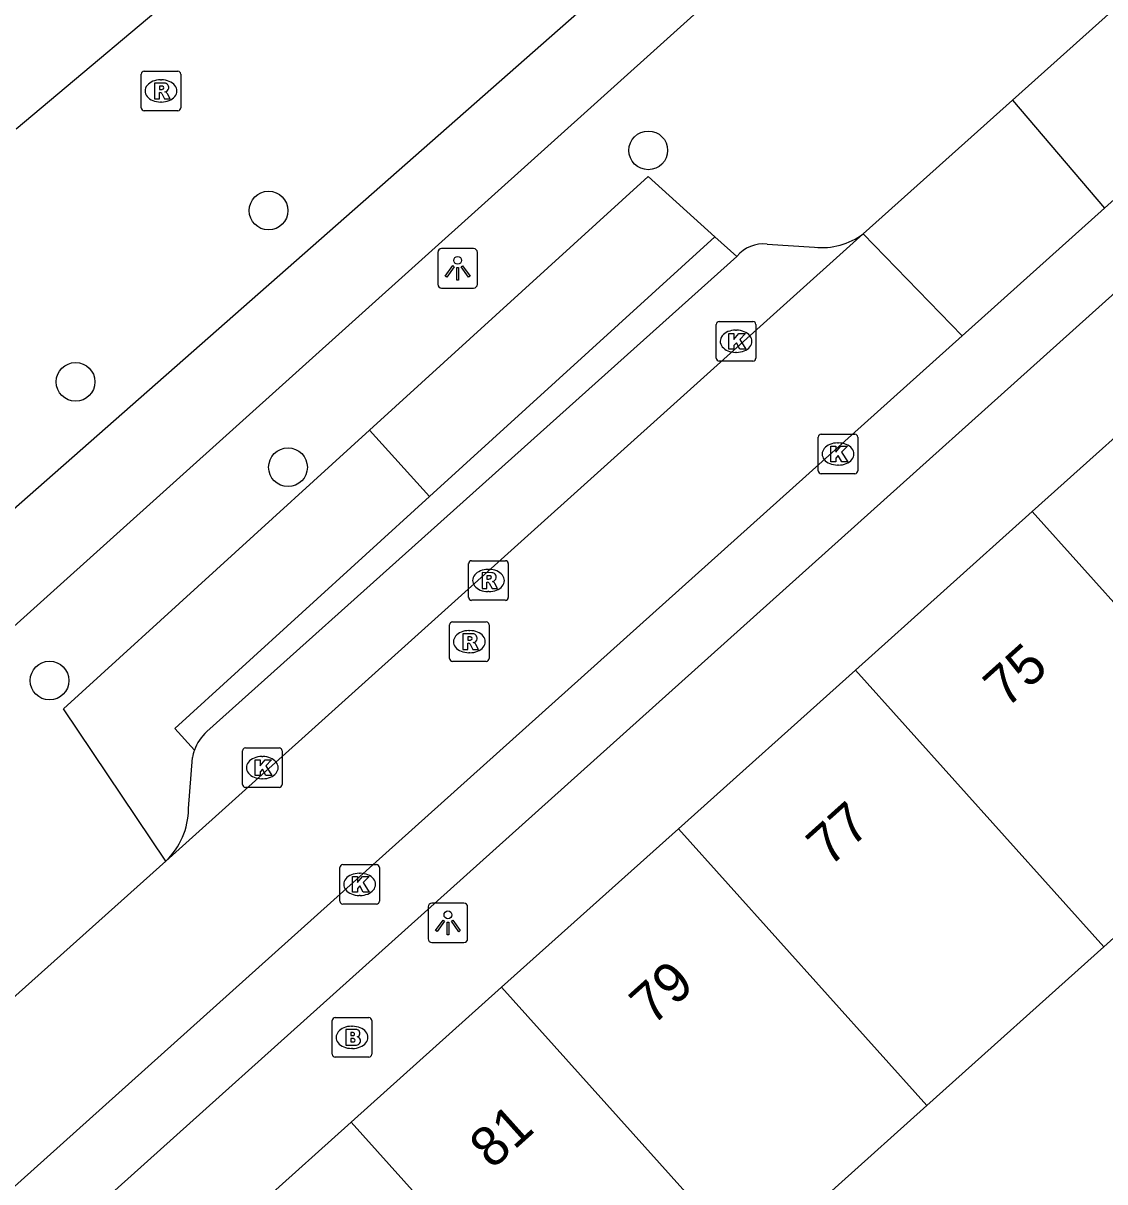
# Model space of a CAD drawing. Extents: x 162172 to 163187, y 382874 to 383684.
# Drawn here: x 162784.58 to 162811.9, y 383341 to 383370.27 of the extents above; entities that cross this region are included whole.
import ezdxf

# ---------------------------------------------------------------- set-up
doc = ezdxf.new("R2010")
doc.units = 0
for name, color, linetype in [('IMGEO_Berm_groen', 7, 'Continuous'), ('IMGEO_Boom', 7, 'Continuous'), ('IMGEO_Brandkraan', 7, 'Continuous'), ('IMGEO_Kolk', 7, 'Continuous'), ('IMGEO_Lichtpunt', 7, 'Continuous'), ('IMGEO_Pand', 7, 'Continuous'), ('IMGEO_Pand_nummerreeks', 7, 'Continuous'), ('IMGEO_Parkeervlak_open', 7, 'Continuous'), ('IMGEO_Rijbaan_lokaal_open', 7, 'Continuous'), ('IMGEO_Rioolput', 7, 'Continuous'), ('IMGEO_Voetpad_halfverhard', 7, 'Continuous'), ('IMGEO_Voetpad_open', 7, 'Continuous')]:
    doc.layers.add(name, color=color, linetype=linetype)

msp = doc.modelspace()

# ---------------------------------------------------------------- linework, layer by layer
at = {"layer": 'IMGEO_Berm_groen'}
for points in [[(162793.329, 383359.988), (162800.361, 383366.393), (162802.051, 383364.873)], [(162788.183, 383349.104), (162785.604, 383352.953), (162793.329, 383359.988)], [(162794.844, 383358.31), (162793.329, 383359.988)]]:
    msp.add_lwpolyline(points, dxfattribs=at)
at = {"layer": 'IMGEO_Boom'}
for centre in [(162800.368, 383367.055), (162790.778, 383365.534), (162785.905, 383361.208), (162791.27, 383359.051), (162785.248, 383353.663)]:
    msp.add_circle(centre, 0.489, dxfattribs=at)
at = {"layer": 'IMGEO_Brandkraan'}
for p, q in [((162792.461, 383345.151), (162793.313, 383345.151)), ((162792.386, 383344.225), (162792.386, 383345.077)), ((162792.874, 383344.931), (162792.899, 383344.931)), ((162793.387, 383345.077), (162793.387, 383344.225)), ((162792.897, 383344.371), (162792.872, 383344.371)), ((162793.313, 383344.151), (162792.461, 383344.151))]:
    msp.add_line(p, q, dxfattribs=at)
for points in [[(162792.461, 383345.151), (162793.313, 383345.151)], [(162792.386, 383344.225), (162792.386, 383345.077)], [(162792.734, 383344.851), (162792.734, 383344.451), (162792.947, 383344.451)], [(162792.965, 383344.851), (162792.734, 383344.851)], [(162793.387, 383345.077), (162793.387, 383344.225)], [(162792.913, 383344.77), (162792.859, 383344.77), (162792.859, 383344.694)], [(162792.859, 383344.694), (162792.912, 383344.694)], [(162792.921, 383344.618), (162792.859, 383344.618), (162792.859, 383344.537)], [(162792.859, 383344.537), (162792.921, 383344.537)], [(162793.313, 383344.151), (162792.461, 383344.151)]]:
    msp.add_lwpolyline(points, dxfattribs=at)
for centre, radius, start, end in [((162792.463, 383345.075), 0.0765, 91.552, 178.448), ((162792.463, 383345.075), 0.0765, 91.552, 178.448), ((162793.311, 383345.075), 0.0765, 1.552, 88.448), ((162793.311, 383345.075), 0.0765, 1.552, 88.448), ((162792.969, 383344.706), 0.145, 59.4692, 91.5367), ((162792.994, 383344.753), 0.0922, 285.5137, 58.1501), ((162792.914, 383344.732), 0.0379, 267.8285, 90.9355), ((162792.922, 383344.577), 0.0404, 269.8759, 90.5077), ((162792.999, 383344.561), 0.105, 301.3115, 78.989), ((162792.953, 383344.702), 0.251, 268.6676, 293.5347), ((162792.463, 383344.227), 0.0765, 181.552, 268.448), ((162792.463, 383344.227), 0.0765, 181.552, 268.448), ((162793.311, 383344.227), 0.0765, 271.552, 358.448), ((162793.311, 383344.227), 0.0765, 271.552, 358.448)]:
    msp.add_arc(centre, radius, start, end, dxfattribs=at)
for centre, major_axis, ratio, start_param, end_param in [((162792.873, 383344.651), (-0.387, 0.002), 0.722429, 4.712389, 7.853982), ((162792.898, 383344.651), (-0.39, 0.002), 0.717154, 1.570796, 4.712389)]:
    msp.add_ellipse(centre, major_axis=major_axis, ratio=ratio, start_param=start_param, end_param=end_param, dxfattribs=at)
at = {"layer": 'IMGEO_Kolk'}
for p, q in [((162802.159, 383362.733), (162803.011, 383362.733)), ((162802.084, 383361.807), (162802.084, 383362.659)), ((162802.572, 383362.513), (162802.597, 383362.513)), ((162803.085, 383362.659), (162803.085, 383361.807)), ((162802.595, 383361.953), (162802.57, 383361.953)), ((162803.011, 383361.733), (162802.159, 383361.733)), ((162804.659, 383358.96), (162804.659, 383359.812)), ((162804.734, 383359.886), (162805.586, 383359.886)), ((162805.66, 383359.812), (162805.66, 383358.96)), ((162805.147, 383359.666), (162805.172, 383359.666)), ((162805.586, 383358.886), (162804.734, 383358.886)), ((162805.17, 383359.106), (162805.145, 383359.106)), ((162790.119, 383351.038), (162790.119, 383351.89)), ((162790.194, 383351.964), (162791.046, 383351.964)), ((162791.12, 383351.89), (162791.12, 383351.038)), ((162790.607, 383351.744), (162790.632, 383351.744)), ((162790.63, 383351.184), (162790.605, 383351.184)), ((162791.046, 383350.964), (162790.194, 383350.964)), ((162792.578, 383348.089), (162792.578, 383348.941)), ((162792.653, 383349.015), (162793.505, 383349.015)), ((162793.579, 383348.941), (162793.579, 383348.089)), ((162793.066, 383348.795), (162793.091, 383348.795)), ((162793.089, 383348.235), (162793.064, 383348.235)), ((162793.505, 383348.015), (162792.653, 383348.015))]:
    msp.add_line(p, q, dxfattribs=at)
for points in [[(162802.159, 383362.733), (162803.011, 383362.733)], [(162802.084, 383361.807), (162802.084, 383362.659)], [(162802.405, 383362.433), (162802.528, 383362.433), (162802.528, 383362.282), (162802.658, 383362.433), (162802.822, 383362.433), (162802.676, 383362.282), (162802.829, 383362.033), (162802.677, 383362.033), (162802.592, 383362.197), (162802.528, 383362.13), (162802.528, 383362.033), (162802.405, 383362.033), (162802.405, 383362.433)], [(162803.085, 383362.659), (162803.085, 383361.807)], [(162803.011, 383361.733), (162802.159, 383361.733)], [(162804.659, 383358.96), (162804.659, 383359.812)], [(162804.734, 383359.886), (162805.586, 383359.886)], [(162805.66, 383359.812), (162805.66, 383358.96)], [(162804.98, 383359.586), (162805.103, 383359.586), (162805.103, 383359.435), (162805.233, 383359.586), (162805.397, 383359.586), (162805.251, 383359.435), (162805.404, 383359.186), (162805.252, 383359.186), (162805.167, 383359.35), (162805.103, 383359.283), (162805.103, 383359.186), (162804.98, 383359.186), (162804.98, 383359.586)], [(162805.586, 383358.886), (162804.734, 383358.886)], [(162790.119, 383351.038), (162790.119, 383351.89)], [(162790.194, 383351.964), (162791.046, 383351.964)], [(162791.12, 383351.89), (162791.12, 383351.038)], [(162790.44, 383351.664), (162790.563, 383351.664), (162790.563, 383351.513), (162790.693, 383351.664), (162790.857, 383351.664), (162790.711, 383351.513), (162790.864, 383351.264), (162790.712, 383351.264), (162790.627, 383351.428), (162790.563, 383351.361), (162790.563, 383351.264), (162790.44, 383351.264), (162790.44, 383351.664)], [(162791.046, 383350.964), (162790.194, 383350.964)], [(162792.578, 383348.089), (162792.578, 383348.941)], [(162792.653, 383349.015), (162793.505, 383349.015)], [(162793.579, 383348.941), (162793.579, 383348.089)], [(162792.899, 383348.715), (162793.022, 383348.715), (162793.022, 383348.564), (162793.152, 383348.715), (162793.316, 383348.715), (162793.17, 383348.564), (162793.323, 383348.315), (162793.171, 383348.315), (162793.086, 383348.479), (162793.022, 383348.412), (162793.022, 383348.315), (162792.899, 383348.315), (162792.899, 383348.715)], [(162793.505, 383348.015), (162792.653, 383348.015)]]:
    msp.add_lwpolyline(points, dxfattribs=at)
for centre, start, end in [((162802.161, 383362.657), 91.552, 178.448), ((162802.161, 383362.657), 91.552, 178.448), ((162803.009, 383362.657), 1.552, 88.448), ((162803.009, 383362.657), 1.552, 88.448), ((162802.161, 383361.809), 181.552, 268.448), ((162802.161, 383361.809), 181.552, 268.448), ((162803.009, 383361.809), 271.552, 358.448), ((162803.009, 383361.809), 271.552, 358.448), ((162804.736, 383359.81), 91.552, 178.448), ((162804.736, 383359.81), 91.552, 178.448), ((162805.584, 383359.81), 1.552, 88.448), ((162805.584, 383359.81), 1.552, 88.448), ((162804.736, 383358.962), 181.552, 268.448), ((162804.736, 383358.962), 181.552, 268.448), ((162805.584, 383358.962), 271.552, 358.448), ((162805.584, 383358.962), 271.552, 358.448), ((162790.196, 383351.888), 91.552, 178.448), ((162790.196, 383351.888), 91.552, 178.448), ((162791.044, 383351.888), 1.552, 88.448), ((162791.044, 383351.888), 1.552, 88.448), ((162790.196, 383351.04), 181.552, 268.448), ((162790.196, 383351.04), 181.552, 268.448), ((162791.044, 383351.04), 271.552, 358.448), ((162791.044, 383351.04), 271.552, 358.448), ((162792.655, 383348.939), 91.552, 178.448), ((162792.655, 383348.939), 91.552, 178.448), ((162793.503, 383348.939), 1.552, 88.448), ((162793.503, 383348.939), 1.552, 88.448), ((162792.655, 383348.091), 181.552, 268.448), ((162792.655, 383348.091), 181.552, 268.448), ((162793.503, 383348.091), 271.552, 358.448), ((162793.503, 383348.091), 271.552, 358.448)]:
    msp.add_arc(centre, 0.0765, start, end, dxfattribs=at)
for centre, major_axis, ratio, start_param, end_param in [((162802.571, 383362.233), (-0.387, 0.002), 0.722429, 4.712389, 7.853982), ((162802.596, 383362.233), (-0.39, 0.002), 0.717154, 1.570796, 4.712389), ((162805.146, 383359.386), (-0.387, 0.002), 0.722429, 4.712389, 7.853982), ((162805.171, 383359.386), (-0.39, 0.002), 0.717154, 1.570796, 4.712389), ((162790.606, 383351.464), (-0.387, 0.002), 0.722429, 4.712389, 7.853982), ((162790.631, 383351.464), (-0.39, 0.002), 0.717154, 1.570796, 4.712389), ((162793.065, 383348.515), (-0.387, 0.002), 0.722429, 4.712389, 7.853982), ((162793.09, 383348.515), (-0.39, 0.002), 0.717154, 1.570796, 4.712389)]:
    msp.add_ellipse(centre, major_axis=major_axis, ratio=ratio, start_param=start_param, end_param=end_param, dxfattribs=at)
at = {"layer": 'IMGEO_Lichtpunt'}
for p, q in [((162795.055, 383364.479), (162795.055, 383363.672)), ((162795.055, 383364.479), (162795.055, 383363.672)), ((162795.957, 383364.574), (162795.149, 383364.574)), ((162795.957, 383364.574), (162795.149, 383364.574)), ((162796.051, 383363.672), (162796.051, 383364.479)), ((162796.051, 383363.672), (162796.051, 383364.479)), ((162795.149, 383363.578), (162795.957, 383363.578)), ((162795.149, 383363.578), (162795.957, 383363.578)), ((162795.712, 383348.042), (162794.904, 383348.042)), ((162795.712, 383348.042), (162794.904, 383348.042)), ((162794.81, 383347.947), (162794.81, 383347.14)), ((162794.81, 383347.947), (162794.81, 383347.14)), ((162795.806, 383347.14), (162795.806, 383347.947)), ((162795.806, 383347.14), (162795.806, 383347.947)), ((162794.904, 383347.046), (162795.712, 383347.046)), ((162794.904, 383347.046), (162795.712, 383347.046))]:
    msp.add_line(p, q, dxfattribs=at)
for points in [[(162795.429, 383364.143), (162795.468, 383364.115), (162795.28, 383363.853), (162795.242, 383363.88), (162795.429, 383364.143)], [(162795.641, 383364.115), (162795.679, 383364.142), (162795.866, 383363.88), (162795.827, 383363.852), (162795.641, 383364.115)], [(162795.531, 383364.095), (162795.578, 383364.095), (162795.578, 383363.773), (162795.531, 383363.773), (162795.531, 383364.095)], [(162795.184, 383347.611), (162795.223, 383347.583), (162795.035, 383347.321), (162794.997, 383347.348), (162795.184, 383347.611)], [(162795.286, 383347.563), (162795.333, 383347.563), (162795.333, 383347.241), (162795.286, 383347.241), (162795.286, 383347.563)], [(162795.396, 383347.583), (162795.434, 383347.61), (162795.621, 383347.348), (162795.582, 383347.32), (162795.396, 383347.583)]]:
    msp.add_lwpolyline(points, dxfattribs=at)
for centre in [(162795.554, 383364.277), (162795.309, 383347.745)]:
    msp.add_circle(centre, 0.0994, dxfattribs=at)
for centre, start, end in [((162795.149, 383364.479), 90, 180), ((162795.149, 383364.479), 90, 180), ((162795.957, 383364.479), 0, 90), ((162795.957, 383364.479), 0, 90), ((162795.149, 383363.672), 180, 270), ((162795.149, 383363.672), 180, 270), ((162795.957, 383363.672), 270, 0), ((162795.957, 383363.672), 270, 360), ((162794.904, 383347.947), 90, 180), ((162794.904, 383347.947), 90, 180), ((162795.712, 383347.947), 0, 90), ((162795.712, 383347.947), 0, 90), ((162794.904, 383347.14), 180, 270), ((162794.904, 383347.14), 180, 270), ((162795.712, 383347.14), 270, 0), ((162795.712, 383347.14), 270, 360)]:
    msp.add_arc(centre, 0.0946, start, end, dxfattribs=at)
at = {"layer": 'IMGEO_Pand'}
for points in [[(162813.86, 383361.339), (162810.063, 383357.934)], [(162810.063, 383357.934), (162805.597, 383353.928)], [(162810.063, 383357.934), (162816.335, 383350.942)], [(162801.13, 383349.921), (162805.597, 383353.928)], [(162805.597, 383353.928), (162811.869, 383346.935)], [(162816.335, 383350.942), (162811.869, 383346.935)], [(162796.664, 383345.915), (162801.13, 383349.921)], [(162801.13, 383349.921), (162807.403, 383342.928)], [(162811.869, 383346.935), (162807.403, 383342.928)], [(162796.664, 383345.915), (162792.867, 383342.51)], [(162802.937, 383338.921), (162796.664, 383345.915)], [(162807.403, 383342.928), (162802.937, 383338.921)], [(162792.867, 383342.51), (162788.4, 383338.504)], [(162799.141, 383335.515), (162792.867, 383342.51)]]:
    msp.add_lwpolyline(points, dxfattribs=at)
at = {"layer": 'IMGEO_Parkeervlak_open'}
for points in [[(162803.369, 383364.689), (162804.563, 383364.61)], [(162788.756, 383350.428), (162788.856, 383351.722)]]:
    msp.add_lwpolyline(points, dxfattribs=at)
for centre, radius, start, end in [((162804.756, 383366.343), 1.743, 263.6461, 306.707), ((162803.279, 383363.811), 0.883, 84.1262, 140.0165), ((162790.113, 383351.483), 1.28, 160.7655, 169.2548), ((162786.932, 383350.431), 1.824, 313.3011, 359.895)]:
    msp.add_arc(centre, radius, start, end, dxfattribs=at)
at = {"layer": 'IMGEO_Rijbaan_lokaal_open'}
for points in [[(162811.886, 383365.593), (162843.693, 383394.145)], [(162809.569, 383368.324), (162817.637, 383375.567)], [(162784.406, 383367.598), (162789.192, 383371.636), (162790.812, 383373.137)], [(162805.798, 383364.945), (162809.569, 383368.324)], [(162809.569, 383368.324), (162811.886, 383365.593)], [(162811.886, 383365.593), (162808.297, 383362.372)], [(162788.183, 383349.104), (162805.798, 383364.945)], [(162805.798, 383364.945), (162808.297, 383362.372)], [(162808.297, 383362.372), (162752.534, 383312.314)], [(162750.185, 383314.921), (162765.945, 383329.187), (162788.183, 383349.104)]]:
    msp.add_lwpolyline(points, dxfattribs=at)
at = {"layer": 'IMGEO_Rioolput'}
for p, q in [((162787.562, 383368.13), (162787.562, 383368.982)), ((162787.637, 383369.056), (162788.489, 383369.056)), ((162788.05, 383368.836), (162788.075, 383368.836)), ((162788.563, 383368.982), (162788.563, 383368.13)), ((162788.073, 383368.276), (162788.048, 383368.276)), ((162788.489, 383368.056), (162787.637, 383368.056)), ((162795.832, 383355.764), (162795.832, 383356.616)), ((162795.907, 383356.69), (162796.759, 383356.69)), ((162796.833, 383356.616), (162796.833, 383355.764)), ((162796.32, 383356.47), (162796.345, 383356.47)), ((162796.759, 383355.69), (162795.907, 383355.69)), ((162796.343, 383355.91), (162796.318, 383355.91)), ((162795.349, 383354.22), (162795.349, 383355.072)), ((162795.424, 383355.146), (162796.276, 383355.146)), ((162796.35, 383355.072), (162796.35, 383354.22)), ((162795.837, 383354.926), (162795.862, 383354.926)), ((162795.86, 383354.366), (162795.835, 383354.366)), ((162796.276, 383354.146), (162795.424, 383354.146))]:
    msp.add_line(p, q, dxfattribs=at)
for points in [[(162787.562, 383368.13), (162787.562, 383368.982)], [(162787.637, 383369.056), (162788.489, 383369.056)], [(162788.563, 383368.982), (162788.563, 383368.13)], [(162788.151, 383368.754), (162787.899, 383368.756), (162787.899, 383368.356)], [(162788.077, 383368.675), (162788.023, 383368.675), (162788.023, 383368.594)], [(162788.023, 383368.594), (162788.075, 383368.594)], [(162787.899, 383368.356), (162788.023, 383368.356), (162788.023, 383368.518), (162788.034, 383368.518)], [(162788.081, 383368.489), (162788.152, 383368.356), (162788.292, 383368.356), (162788.227, 383368.482)], [(162788.489, 383368.056), (162787.637, 383368.056)], [(162795.832, 383355.764), (162795.832, 383356.616)], [(162795.907, 383356.69), (162796.759, 383356.69)], [(162796.833, 383356.616), (162796.833, 383355.764)], [(162796.421, 383356.388), (162796.169, 383356.39), (162796.169, 383355.99)], [(162796.347, 383356.309), (162796.293, 383356.309), (162796.293, 383356.228)], [(162796.169, 383355.99), (162796.293, 383355.99), (162796.293, 383356.152), (162796.304, 383356.152)], [(162796.293, 383356.228), (162796.345, 383356.228)], [(162796.351, 383356.123), (162796.422, 383355.99), (162796.562, 383355.99), (162796.497, 383356.116)], [(162796.759, 383355.69), (162795.907, 383355.69)], [(162795.349, 383354.22), (162795.349, 383355.072)], [(162795.424, 383355.146), (162796.276, 383355.146)], [(162796.35, 383355.072), (162796.35, 383354.22)], [(162795.938, 383354.844), (162795.686, 383354.846), (162795.686, 383354.446)], [(162795.686, 383354.446), (162795.81, 383354.446), (162795.81, 383354.608), (162795.821, 383354.608)], [(162795.864, 383354.765), (162795.81, 383354.765), (162795.81, 383354.684)], [(162795.81, 383354.684), (162795.862, 383354.684)], [(162795.868, 383354.579), (162795.939, 383354.446), (162796.079, 383354.446), (162796.014, 383354.572)], [(162796.276, 383354.146), (162795.424, 383354.146)]]:
    msp.add_lwpolyline(points, dxfattribs=at)
for centre, radius, start, end in [((162787.639, 383368.98), 0.0765, 91.552, 178.448), ((162787.639, 383368.98), 0.0765, 91.552, 178.448), ((162788.487, 383368.98), 0.0765, 1.552, 88.448), ((162788.487, 383368.98), 0.0765, 1.552, 88.448), ((162788.059, 383368.783), 0.19, 274.7715, 282.9687), ((162788.083, 383368.579), 0.0964, 77.0061, 93.1865), ((162788.097, 383368.636), 0.0378, 276.6634, 79.6772), ((162788.15, 383368.644), 0.109, 350.3612, 89.416), ((162788.148, 383368.644), 0.112, 277.5842, 350.9817), ((162788.132, 383368.429), 0.108, 29.5134, 73.7905), ((162788.033, 383368.465), 0.0533, 26.0293, 88.6989), ((162787.639, 383368.132), 0.0765, 181.552, 268.448), ((162787.639, 383368.132), 0.0765, 181.552, 268.448), ((162788.487, 383368.132), 0.0765, 271.552, 358.448), ((162788.487, 383368.132), 0.0765, 271.552, 358.448), ((162795.909, 383356.614), 0.0765, 91.552, 178.448), ((162795.909, 383356.614), 0.0765, 91.552, 178.448), ((162796.757, 383356.614), 0.0765, 1.552, 88.448), ((162796.757, 383356.614), 0.0765, 1.552, 88.448), ((162796.353, 383356.213), 0.0964, 77.0061, 93.1865), ((162796.367, 383356.27), 0.0378, 276.6634, 79.6772), ((162796.42, 383356.278), 0.109, 350.3612, 89.416), ((162796.418, 383356.278), 0.112, 277.5842, 350.9817), ((162796.303, 383356.099), 0.0533, 26.0293, 88.6989), ((162796.329, 383356.417), 0.19, 274.7715, 282.9687), ((162796.402, 383356.063), 0.108, 29.5134, 73.7905), ((162795.909, 383355.766), 0.0765, 181.552, 268.448), ((162795.909, 383355.766), 0.0765, 181.552, 268.448), ((162796.757, 383355.766), 0.0765, 271.552, 358.448), ((162796.757, 383355.766), 0.0765, 271.552, 358.448), ((162795.426, 383355.07), 0.0765, 91.552, 178.448), ((162795.426, 383355.07), 0.0765, 91.552, 178.448), ((162796.274, 383355.07), 0.0765, 1.552, 88.448), ((162796.274, 383355.07), 0.0765, 1.552, 88.448), ((162795.937, 383354.734), 0.109, 350.3612, 89.416), ((162795.82, 383354.555), 0.0533, 26.0293, 88.6989), ((162795.846, 383354.873), 0.19, 274.7715, 282.9687), ((162795.87, 383354.669), 0.0964, 77.0061, 93.1865), ((162795.884, 383354.726), 0.0378, 276.6634, 79.6772), ((162795.935, 383354.734), 0.112, 277.5842, 350.9817), ((162795.919, 383354.519), 0.108, 29.5134, 73.7905), ((162795.426, 383354.222), 0.0765, 181.552, 268.448), ((162795.426, 383354.222), 0.0765, 181.552, 268.448), ((162796.274, 383354.222), 0.0765, 271.552, 358.448), ((162796.274, 383354.222), 0.0765, 271.552, 358.448)]:
    msp.add_arc(centre, radius, start, end, dxfattribs=at)
for centre, major_axis, ratio, start_param, end_param in [((162788.049, 383368.556), (-0.387, 0.002), 0.722429, 4.712389, 7.853982), ((162788.074, 383368.556), (-0.39, 0.002), 0.717154, 1.570796, 4.712389), ((162796.319, 383356.19), (-0.387, 0.002), 0.722429, 4.712389, 7.853982), ((162796.344, 383356.19), (-0.39, 0.002), 0.717154, 1.570796, 4.712389), ((162795.836, 383354.646), (-0.387, 0.002), 0.722429, 4.712389, 7.853982), ((162795.861, 383354.646), (-0.39, 0.002), 0.717154, 1.570796, 4.712389)]:
    msp.add_ellipse(centre, major_axis=major_axis, ratio=ratio, start_param=start_param, end_param=end_param, dxfattribs=at)
at = {"layer": 'IMGEO_Voetpad_halfverhard'}
for points in [[(162800.736, 383372.427), (162775.641, 383350.343)], [(162777.312, 383348.702), (162802.438, 383371.316)]]:
    msp.add_lwpolyline(points, dxfattribs=at)
at = {"layer": 'IMGEO_Voetpad_open'}
for points in [[(162842.607, 383390.811), (162755.461, 383312.558)], [(162802.051, 383364.873), (162794.844, 383358.31)], [(162802.051, 383364.873), (162802.602, 383364.378)], [(162789.217, 383352.373), (162795.288, 383357.818), (162802.602, 383364.378)], [(162794.844, 383358.31), (162788.409, 383352.45), (162788.905, 383351.905)]]:
    msp.add_lwpolyline(points, dxfattribs=at)
msp.add_arc((162790.004, 383351.51), 1.168, 132.3759, 160.244, dxfattribs=at)

# ---------------------------------------------------------------- texts
at = {"layer": 'IMGEO_Pand_nummerreeks'}
for s, p in [('75', (162809.407, 383352.939)), ('77', (162804.94, 383348.933)), ('79', (162800.472, 383344.925)), ('81', (162796.425, 383341.295))]:
    msp.add_text(s, height=1, rotation=41.8897, dxfattribs=at).set_placement(p)

doc.saveas('drawing.dxf')
